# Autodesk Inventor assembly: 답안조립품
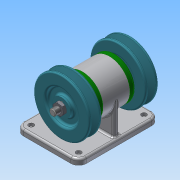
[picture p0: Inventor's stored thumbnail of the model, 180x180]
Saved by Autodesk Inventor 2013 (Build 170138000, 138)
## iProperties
Created: 2019-09
Part Number: 답안조립품
Document SubType Name: Assembly
Designer: Administrator
Author: Administrator
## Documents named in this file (10)
- C:\Users\Administrator\Desktop\490904V1040\답안조립품.iam
- C:\Users\Administrator\Desktop\490904V1040\본체.ipt
- C:\Users\Administrator\Desktop\490904V1040\V-벨트풀리.ipt
- C:\Users\Administrator\Desktop\490904V1040\너트 M10x1.ipt
- C:\Users\Administrator\Desktop\490904V1040\베어링 6004.ipt
- C:\Users\Administrator\Desktop\490904V1040\볼트 M4.ipt
- C:\Users\Administrator\Desktop\490904V1040\오일 실 17 30 5.ipt
- C:\Users\Administrator\Desktop\490904V1040\축.ipt
- C:\Users\Administrator\Desktop\490904V1040\커버.ipt
- C:\Users\Administrator\Desktop\490904V1040\키 5 x 5 x 12.ipt
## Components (2 placed, 1 different names)
1. V-벨트풀리:1 — 각도:1
2. V-벨트풀리:2 — 각도:2
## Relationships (2: Angle 2)
- 각도:1 [Angle]: V-벨트풀리:1
- 각도:2 [Angle]: V-벨트풀리:2
